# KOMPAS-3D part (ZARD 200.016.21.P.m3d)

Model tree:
1. Поверхность без истории:1
2. Поверхность без истории:2
3. Поверхность без истории:3
4. Поверхность без истории:4
5. Поверхность без истории:5
6. Поверхность без истории:6
7. Поверхность без истории:7
8. Поверхность без истории:8
9. Поверхность без истории:9
10. Поверхность без истории:10
11. Поверхность без истории:11
12. Поверхность без истории:12
13. Поверхность без истории:13
14. Поверхность без истории:14
15. Поверхность без истории:15
16. Поверхность без истории:16
17. Поверхность без истории:17
18. Поверхность без истории:18
19. Поверхность без истории:19
20. Поверхность без истории:20
21. Поверхность без истории:21
22. Поверхность без истории:22
23. Поверхность без истории:23
24. Поверхность без истории:24
25. Поверхность без истории:25
26. Поверхность без истории:26
27. Поверхность без истории:27
28. Поверхность без истории:28
29. Поверхность без истории:29
30. Поверхность без истории:30
31. Поверхность без истории:31
32. Поверхность без истории:32
33. Поверхность без истории:33
34. Поверхность без истории:34
35. Поверхность без истории:35
36. Поверхность без истории:36
37. Поверхность без истории:37
38. Поверхность без истории:38
39. Поверхность без истории:39
40. Поверхность без истории:40
41. Поверхность без истории:41
42. Поверхность без истории:42
43. Поверхность без истории:43
44. Поверхность без истории:44
45. Поверхность без истории:45
46. Поверхность без истории:46
47. Поверхность без истории:47
48. Поверхность без истории:48
49. Поверхность без истории:49
50. Поверхность без истории:50
51. Поверхность без истории:51
52. Поверхность без истории:52
53. Поверхность без истории:53
54. Поверхность без истории:54
55. Поверхность без истории:55
56. Поверхность без истории:56
57. Поверхность без истории:57
58. Поверхность без истории:58
59. Поверхность без истории:59
60. Поверхность без истории:60
61. Поверхность без истории:61
62. Поверхность без истории:62
63. Поверхность без истории:63
64. Поверхность без истории:64
65. Поверхность без истории:65
66. Поверхность без истории:66
67. Поверхность без истории:67
68. Поверхность без истории:68
69. Поверхность без истории:69
70. Поверхность без истории:70
71. Поверхность без истории:71
72. Поверхность без истории:72
73. Поверхность без истории:73
74. Поверхность без истории:74
75. Поверхность без истории:75
76. Поверхность без истории:76
77. Поверхность без истории:77
78. Поверхность без истории:78
79. Поверхность без истории:79
80. Поверхность без истории:80
81. Поверхность без истории:81
82. Поверхность без истории:82
83. Поверхность без истории:83
84. Поверхность без истории:84
85. Поверхность без истории:85
86. Поверхность без истории:86
87. Поверхность без истории:87
88. Поверхность без истории:88
89. Поверхность без истории:89
90. Поверхность без истории:90
91. Поверхность без истории:91
92. Поверхность без истории:92
93. Поверхность без истории:93
94. Поверхность без истории:94
95. Поверхность без истории:95
96. Поверхность без истории:96
97. Поверхность без истории:97
98. Поверхность без истории:98
99. Поверхность без истории:99
100. Поверхность без истории:100
101. Поверхность без истории:101
102. Поверхность без истории:102
103. Поверхность без истории:103

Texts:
  ЗАРД 200-016-21-Р( АВ550) КП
